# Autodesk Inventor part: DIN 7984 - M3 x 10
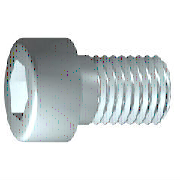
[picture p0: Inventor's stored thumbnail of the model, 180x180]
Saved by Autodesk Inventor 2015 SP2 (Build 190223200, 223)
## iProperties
IsCustomPart: 0
Created: 2012-02
Part Number: DIN 7984 - M3 x 10
Material: Stahl, weich
Description: Zylinderkopfschraube
Document SubType Name: Modeling
Standard: DIN 7984
Designer: SteffenHaase
Standard Revision: 1985
Standards Organization: DIN
Language: de-DE
Size Designation: M3 x 10
Categories: <MemberInstance><Categories><Category DisplayName="Verbindungselemente" InternalName="e4da775c-781d-43d5-af7c-5136215cf5a6" Mnemonic="FSTN"><Category DisplayNam
Density: 7.85 g/cm^3
Appearance: Halbpoliert
Author: SteffenHaase
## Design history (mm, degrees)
sketch "Skizze1"
  geometry: L1 (0.167, 0)-(10, 0); L2 (10, 0)-(10, 1.5); L3 (10, 1.5)-(1.5, 1.5); L4 (1.5, 1.5)-(1.193, 1.5); L5 (1.193, 1.5)-(0, 1.5); L6 (0, 1.5)-(0, 2.75); L7 (0, 2.75)-(-2, 2.75); L8 (-2, 2.75)-(-2, 1.155); L9 (-2, 1.155)-(-0.5, 1.155); L10 (-0.5, 1.155)-(0.167, 0); L11 (-4.4, 0)-(12.4, 0) reference; L12 (0, -0.55)-(0, 3.3) reference; L13 (1.5, 1.5)-(0, 1.5)
  constraints: 22 end point, 6 parallel, 2 collinear, 2 perpendicular, 1 horizontal, 1 point on line
  dimensions: "d1" = 8.5 distance from line of L3.end L2 (= GEL); "d2" = 0.30683 distance of L4.end L3.end (computed from GAL); "d3" = 2 distance between parallel lines of L8 L6 (= KOH); "d4" = 1.5 distance of L8.end L9.end (= INTI); "d5" = 60 deg angle of L10 L1; "d6" = 3 diameter of L3 L1 (= GD); "d7" = 3 diameter of L5 L1 (= BDM); "d8" = 2.3094 diameter of L9 L1 (= 1.1547 x SW); "d9" = 5.5 diameter of L7 L1 (= KOD); "d26" = 10 distance between parallel lines of L12 L2 (= NLG)
revolve "Körper" sketch "Skizze1" stored, may be unused: angle "d10" = 90 deg
sketch "Skizze2"
  geometry: L1 (0, -3.85)-(0, 3.85) reference; L2 (-3.85, 0)-(3.85, 0) reference; L3 (1.155, 0)-(0.577, -1); L4 (0.577, -1)-(-0.577, -1); L5 (-0.577, -1)-(-1.155, 0); L6 (-1.155, 0)-(-0.577, 1); L7 (-0.577, 1)-(0.577, 1); L8 (0.577, 1)-(1.155, 0); 2 further points
  constraints: 12 end point, 1 coincident, 1 horizontal alignment, 1 point on line, 12 other
extrude "Loch" join sketch "Skizze2" stored distance "d11" = 10; taper "d12" = 0 deg
workplane "Work Plane1"
fillet "Fillet2" dims "d30" = 0.1 (= R)
body "Solid1"
fillet "Rundung1" dims "d17" = 0.3 (= RR)
feature "Gewinde" dims "d13" = 8.5 (= GEL), "d14" = 0
chamfer "Fase1" distance "d15" = 0.30673 (= -0.5 x SPD + 0.5 x GD); stored, may be unused: second distance "d16" = 0.30673 (= GUL), angle "d27" = 45 deg
other parameters: "GD" = 3 (= NND) [user parameter; used in 2 equation terms], "NLG" = 10 [user parameter; used in 1 equation term], "GEL" = 8.5 [user parameter; used in 2 equation terms], "KOD" = 5.5 [user parameter; used in 1 equation term], "KOH" = 2 [user parameter; used in 1 equation term], "INTI" = 1.5 [user parameter; used in 1 equation term], "GAL" = 0.30673 (= 0.61345 x PTC) [user parameter; used in 1 equation term], "GUL" = 0.30673 (= 0.61345 x PTC) [user parameter; used in 1 equation term], "BDM" = 3 (= NND) [user parameter; used in 1 equation term], "SW" = 2 [user parameter; used in 2 equation terms], "RR" = 0.3 [user parameter; used in 1 equation term], "SPD" = 2.38655 (= NND - 1.2269 x PTC) [user parameter; used in 1 equation term], "d19" = 0, "d28" = 0, "d29" = 0, "R" = 0.1 [user parameter; used in 1 equation term], "TOA" = 30 deg [user parameter], "GD1" = 2.38655 (= THREADDIA - 1.2269 x PTC) [user parameter], "THREADDIA" = 3 [user parameter; used in 1 equation term], "FAWI" = 45 deg [user parameter], "ANG" = 120 deg [user parameter], "PTC" = 0.5 [user parameter; used in 5 equation terms], "NND" = 3 [user parameter; used in 3 equation terms], "E0" = 2.31 (= 1.155 x SW) [user parameter]
